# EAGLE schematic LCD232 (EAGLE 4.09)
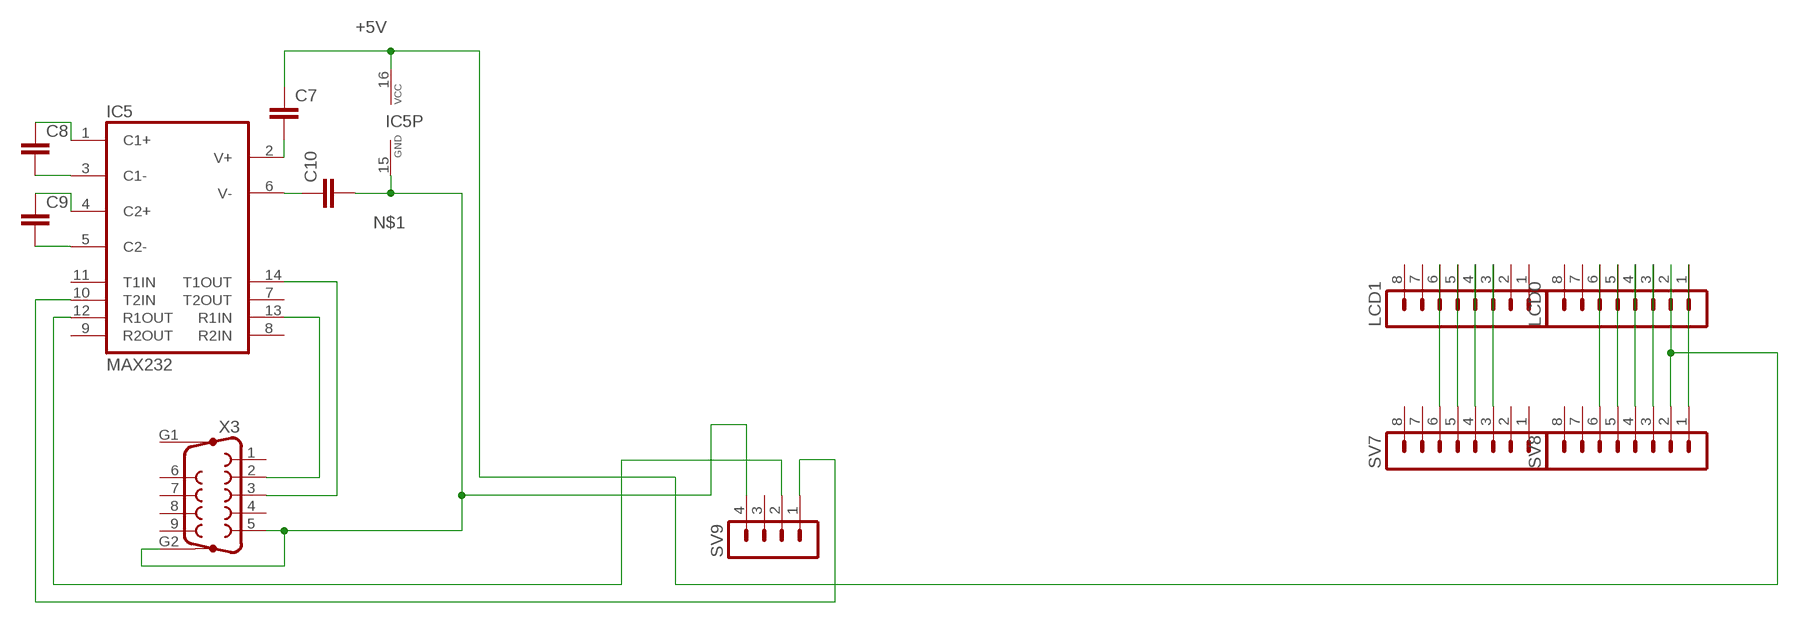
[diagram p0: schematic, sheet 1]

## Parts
C7  C5/5  [C5B5]
C8  C5/5  [C5B5]
C9  C5/5  [C5B5]
C10  C5/5  [C5B5]
IC5  MAX232  [DIL16]
LCD0  MA08-1  [MA08-1]
LCD1  MA08-1  [MA08-1]
SV7  MA08-1  [MA08-1]
SV8  MA08-1  [MA08-1]
SV9  MA04-1  [MA04-1]
X3  F09HP  [F09HP]

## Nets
+5V: C7.1 IC5.16(VCC) LCD0.2 SV8.2
N$1: C10.2 IC5.15(GND) SV9.4 X3.5 X3.G2
N$3: LCD0.5 SV8.5
N$4: LCD0.1 SV8.1
N$14: LCD1.6 SV7.6
N$17: LCD1.5 SV7.5
N$18: LCD1.4 SV7.4
N$19: LCD1.3 SV7.3
N$20: LCD0.3 SV8.3
N$25: LCD0.6 SV8.6
N$26: LCD0.4 SV8.4
N$54: C10.1 IC5.6(V-)
N$55: C7.2 IC5.2(V+)
N$57: C8.1 IC5.1(C1+)
N$58: IC5.13(R1IN) X3.2
N$59: C8.2 IC5.3(C1-)
N$60: C9.1 IC5.4(C2+)
N$61: IC5.12(R1OUT) SV9.2
N$62: IC5.14(T1OUT) X3.3
N$64: IC5.10(T2IN) SV9.1
N$65: C9.2 IC5.5(C2-)
Unconnected: IC5.7(T2OUT) IC5.8(R2IN) IC5.9(R2OUT) IC5.11(T1IN) LCD0.7 LCD0.8 LCD1.1 LCD1.2 LCD1.7 LCD1.8 SV7.1 SV7.2 SV7.7 SV7.8 SV8.7 SV8.8 SV9.3 X3.1 X3.4 X3.6 X3.7 X3.8 X3.9 X3.G1

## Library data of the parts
C7-C10 = capacitor-wima:C: CAPACITOR
IC5 = maxim:MAX232: RS232 TRANSEIVER
LCD0 LCD1 SV7 SV8 = con-lstb:MA08-1: PIN HEADER
SV9 = con-lstb:MA04-1: PIN HEADER
X3 = con-subd:F09HP: SUB-D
